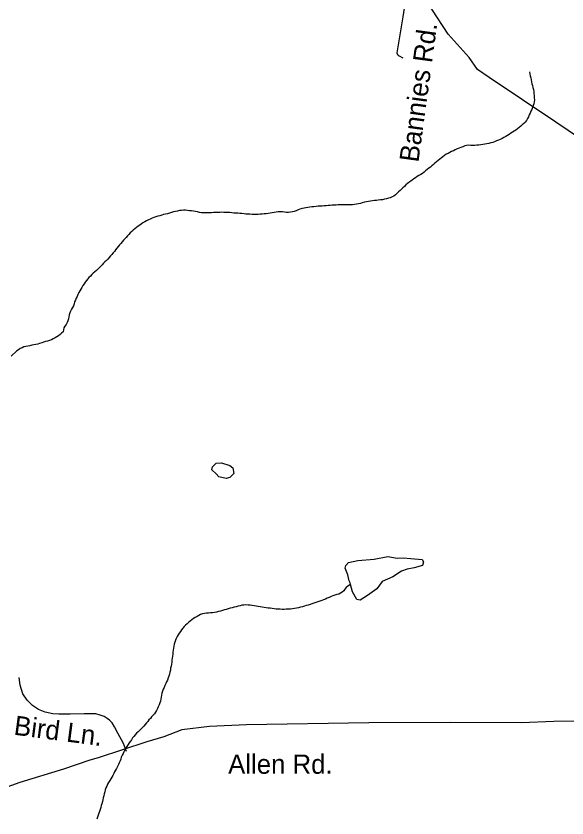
# Model space of a CAD drawing. Extents: x 1950930 to 2061844, y 904556 to 1017002.
# Drawn here: x 1981210 to 1983928, y 931351 to 935305 of the extents above; entities that cross this region are included whole.
import ezdxf

# ---------------------------------------------------------------- set-up
doc = ezdxf.new("R2010")
doc.units = 0
for name, color, linetype in [('Exist Hydrographic Creek Single Shore', 7, 'Continuous'), ('Exist Hydrographic Misc Water Feature', 7, 'Continuous'), ('Exist Road Non-System Type 51', 7, 'Continuous'), ('Exist Road Non-System Type 51 Label', 7, 'Continuous'), ('Exist Road Secondary Type 51 Attributed', 7, 'Continuous'), ('Exist Road Secondary Type 51 Label', 7, 'Continuous')]:
    doc.layers.add(name, color=color, linetype=linetype)

msp = doc.modelspace()

# ---------------------------------------------------------------- linework, layer by layer
at = {"layer": 'Exist Hydrographic Creek Single Shore'}
for points in [[(1983743, 935030.5), (1983745.2, 935020.5), (1983746.9, 935010.4), (1983749.1, 935000.4), (1983751.2, 934990.7), (1983753.4, 934980.7), (1983755.3, 934971.1), (1983757.5, 934961.7), (1983759.8, 934952.1), (1983762.2, 934941.9), (1983764.1, 934932.4), (1983765.3, 934922.5), (1983766.3, 934912.5), (1983766.9, 934901.9), (1983767.6, 934892.1), (1983766.3, 934882.1), (1983764.3, 934872.2), (1983761.8, 934863.3), (1983758.1, 934853.7), (1983754.4, 934843.7), (1983750.3, 934835), (1983746.6, 934825.8), (1983742.3, 934817.2), (1983737.6, 934807.3), (1983732.9, 934799.1), (1983727.6, 934790.2), (1983721.6, 934782.2), (1983715.3, 934774.6), (1983707.7, 934767.7), (1983700.3, 934761.1), (1983692.3, 934754.9), (1983684.3, 934749.3), (1983675.9, 934742.8), (1983667.9, 934738), (1983659.3, 934732.4), (1983650.7, 934726.7), (1983642.7, 934721.5), (1983634.9, 934715.8), (1983625.9, 934710.2), (1983617.1, 934705.5), (1983607.8, 934701.6), (1983599, 934696.9), (1983589.8, 934693), (1983580.8, 934689.1), (1983571.1, 934685.3), (1983561.7, 934681.8), (1983552.3, 934678.9), (1983543, 934676.6), (1983533, 934675.3), (1983522.7, 934672.8), (1983513.1, 934671.4), (1983503.3, 934670), (1983493.2, 934668.7), (1983483.2, 934667.5), (1983473.3, 934666.6), (1983463.5, 934665.9), (1983453.4, 934667.1), (1983442.8, 934667.5), (1983432.9, 934666.6), (1983423.7, 934664.3), (1983414.5, 934660.4), (1983405, 934657.4), (1983395.4, 934653.5), (1983386.8, 934649.6), (1983377.1, 934645.9), (1983367.9, 934640.7), (1983359.1, 934636.8), (1983350.3, 934632.4), (1983341.5, 934627.3), (1983332.6, 934623), (1983324.4, 934617.3), (1983316.4, 934610.8), (1983308.5, 934605.1), (1983300, 934598.7), (1983292.7, 934592.5), (1983284.9, 934586), (1983276.9, 934579.5), (1983269.5, 934573.3), (1983262.1, 934566.7), (1983254.1, 934560.2), (1983246.7, 934554.1), (1983238.9, 934547.5), (1983230.9, 934541.1), (1983223.4, 934535.7), (1983214.9, 934529.3), (1983206.3, 934523.6), (1983197.9, 934518.8), (1983189.7, 934513.2), (1983181.5, 934507.5), (1983173.3, 934501.5), (1983164.7, 934495.9), (1983157.1, 934490.1), (1983148.7, 934483.8), (1983141.1, 934478.4), (1983133.1, 934471.9), (1983126.2, 934465.2), (1983118.6, 934458.2), (1983111.2, 934451.7), (1983104.4, 934444.6), (1983096.6, 934438)], [(1983096.6, 934438), (1983089.3, 934430.6), (1983082.3, 934423.6), (1983074.7, 934417), (1983065.9, 934412.7), (1983056.6, 934408.4), (1983047, 934406.2), (1983037.4, 934404.1), (1983027.1, 934401.9), (1983017.5, 934399.4), (1983007.4, 934398), (1982997.4, 934396.7), (1982987.7, 934395.4), (1982977.9, 934394.9), (1982967.9, 934393.1), (1982958, 934391.8), (1982948.4, 934390.4), (1982938.3, 934389.1), (1982928.5, 934386.5), (1982918.4, 934384.4), (1982909, 934381.3), (1982899.8, 934379.1), (1982889.7, 934377.4), (1982879.7, 934376.1), (1982869.6, 934374.8), (1982859.8, 934374.3), (1982850.2, 934374.5), (1982839.7, 934373.6), (1982830.1, 934373.8), (1982819.8, 934374.3), (1982809.6, 934373.7), (1982799.7, 934373.6), (1982789.9, 934373.1), (1982779.6, 934372.6), (1982769.8, 934371.7), (1982759.9, 934371.2), (1982749.7, 934370.7), (1982739.6, 934369.7), (1982729.6, 934368.4), (1982719.7, 934367.9), (1982709.9, 934367.4), (1982700.1, 934366.9), (1982690, 934365.1), (1982679.8, 934364.7), (1982669.7, 934363.4), (1982659.9, 934362.9), (1982649.8, 934361.1), (1982640.2, 934359.7), (1982630.8, 934358.4), (1982620.9, 934355.4), (1982610.9, 934352), (1982601.8, 934348.9), (1982592.4, 934345.1), (1982582.8, 934341.2), (1982573.5, 934339), (1982563.9, 934337.7), (1982553.7, 934336.8), (1982543.8, 934337), (1982533.8, 934338.2), (1982523.9, 934339.3), (1982513.7, 934339.2), (1982503.8, 934338.7), (1982493.8, 934337.3), (1982483.7, 934336), (1982473.7, 934334.4), (1982464, 934332.9), (1982454.2, 934331.6), (1982444.6, 934330.3), (1982434.1, 934329.4), (1982424.3, 934328), (1982414.4, 934327.5), (1982404.2, 934327.1), (1982394.1, 934326.2), (1982384.9, 934326.4), (1982374.2, 934326.7), (1982364.2, 934327.8), (1982354.5, 934328.1), (1982344.5, 934328.8), (1982334.9, 934329.9), (1982324.4, 934331.1), (1982314.4, 934332.1), (1982304.7, 934332.4), (1982294.7, 934333.1), (1982284.4, 934333.5), (1982274.8, 934334.5), (1982264.9, 934335.6), (1982254.7, 934335.6), (1982244.4, 934335.9), (1982234.4, 934337), (1982224.8, 934337.2), (1982214.9, 934336.3), (1982204.7, 934336.6), (1982194.8, 934336.1), (1982185, 934335.6), (1982174.7, 934334.8), (1982164.5, 934335.1), (1982155, 934334.5), (1982144.8, 934334.1), (1982134.5, 934334), (1982124.9, 934334.2)], [(1982124.9, 934334.2), (1982114.8, 934336.1), (1982105.2, 934338.8), (1982095.8, 934340.6), (1982085.5, 934342.7), (1982075.5, 934344.1), (1982065.4, 934345.2), (1982055.4, 934346.4), (1982045.5, 934347.5), (1982035.7, 934347.8), (1982025.9, 934346.9), (1982016.2, 934345.4), (1982006.2, 934343.3), (1981996.3, 934341.1), (1981986.7, 934339), (1981977.3, 934335.6), (1981967.4, 934333.4), (1981957.6, 934330.4), (1981947.9, 934328.2), (1981938.1, 934326.1), (1981928.9, 934323.4), (1981919, 934320.4), (1981909.2, 934318.3), (1981899.3, 934315.3), (1981890.1, 934311), (1981881.3, 934307.9), (1981872.1, 934304), (1981862.8, 934299.4), (1981853.6, 934295.5), (1981845, 934289.9), (1981836.2, 934285.2), (1981828, 934279.5), (1981820, 934274.3), (1981811.8, 934268.6), (1981803.8, 934262.1), (1981796, 934255.9), (1981788.6, 934249.4), (1981781, 934242), (1981773.6, 934235.8), (1981766.9, 934228.4), (1981759.7, 934221.3), (1981752.9, 934213.8), (1981746.2, 934206.7), (1981739.4, 934199.7), (1981733, 934191.3), (1981726.3, 934184.2), (1981719.9, 934176.2), (1981714, 934169), (1981707.4, 934160.7), (1981701, 934152.7), (1981695.1, 934144.7), (1981689.2, 934137.4), (1981682.8, 934129.5), (1981676.4, 934121.9), (1981669.5, 934114), (1981662.7, 934106.6), (1981655.7, 934099.6), (1981648.6, 934092.9), (1981642, 934085.9), (1981634.8, 934078.8), (1981627.6, 934071.3), (1981620.9, 934064.2), (1981613.7, 934056.8), (1981606.7, 934050.6), (1981598.7, 934044), (1981591.1, 934036.7), (1981583.3, 934030.6), (1981576.6, 934023.1), (1981570, 934016), (1981563.7, 934008.9), (1981557.1, 934000.4), (1981551.2, 933992.5), (1981545.6, 933984.4), (1981539.9, 933976.4), (1981534.5, 933967.3), (1981529.8, 933958.4), (1981524.9, 933949.8), (1981520.2, 933941.6), (1981515.5, 933931.8), (1981511.4, 933922.6), (1981507.5, 933913.9), (1981503, 933904.8), (1981498.9, 933896.1), (1981496.4, 933886.3), (1981493.9, 933876.6), (1981489.4, 933867.5), (1981483.5, 933859.5), (1981478.2, 933850.6), (1981474.9, 933841.3), (1981472.4, 933831.5), (1981470.6, 933822.1), (1981468.3, 933812.3), (1981465.4, 933802.2), (1981461.5, 933793.4), (1981456.6, 933784.4), (1981451.3, 933776.3), (1981446.4, 933767.3), (1981444.3, 933757.5), (1981441.9, 933747.7), (1981434.9, 933741.5)], [(1981434.9, 933741.5), (1981427.5, 933734.9), (1981419.1, 933728.4), (1981411.1, 933723.2), (1981402.5, 933717.6), (1981393.3, 933712.9), (1981384.2, 933707.7), (1981375.4, 933705.1), (1981365.6, 933702.5), (1981355.7, 933699.5), (1981345.9, 933697.4), (1981336.7, 933694.3), (1981326.6, 933690.9), (1981317.2, 933687.9), (1981308, 933685.7), (1981297.7, 933683.5), (1981288.1, 933681.4), (1981278.6, 933678.7), (1981268.4, 933677.5), (1981259, 933675.2), (1981248.9, 933673.2), (1981239.7, 933669.3), (1981230.7, 933665.4), (1981222, 933659.8), (1981213.8, 933654.1), (1981186.6, 933628.3)]]:
    msp.add_lwpolyline(points, dxfattribs=at)
at = {"layer": 'Exist Hydrographic Misc Water Feature'}
for points in [[(1982196.7, 933099.7), (1982224.5, 933102.3), (1982264.7, 933088.5), (1982278.9, 933078.2), (1982285.2, 933050), (1982265.4, 933029.9), (1982247.3, 933024.2), (1982211, 933033.7), (1982196.9, 933048.1), (1982176.8, 933068.2), (1982178.8, 933082.1), (1982196.7, 933099.7)], [(1982860.6, 932502.7), (1982859, 932510.6), (1982853, 932520.9), (1982846.5, 932550.3), (1982834.6, 932582.6), (1982836.4, 932596.6), (1982850.2, 932610.3), (1982896.1, 932620.8), (1982976.3, 932627.2), (1983043.7, 932640), (1983090.1, 932632.6), (1983120.2, 932634.1), (1983158.4, 932631.2), (1983213.7, 932624.8), (1983219.9, 932613.3), (1983216, 932595.2), (1983173.9, 932584.6), (1983140.3, 932578.7), (1983112.2, 932568.8), (1983068.7, 932540.1), (1983017.1, 932517.5), (1982989.2, 932481.1), (1982943.3, 932447.6), (1982907.6, 932424.5), (1982891.8, 932429), (1982869.6, 932466.5), (1982860.6, 932502.7)], [(1982860.6, 932502.7), (1982846.5, 932493.9), (1982839.1, 932487.4), (1982832.9, 932479.4), (1982827, 932471.3), (1982819.8, 932464.3), (1982811.4, 932459.1), (1982802.2, 932455.2), (1982792.7, 932452.2), (1982782.9, 932449.2), (1982773.5, 932446.2), (1982764, 932442.4), (1982755.2, 932438.4), (1982745.6, 932434.2), (1982736.4, 932430.3), (1982726.9, 932427.3), (1982717.9, 932423.4), (1982708.5, 932420.3), (1982698.8, 932416.5), (1982689.4, 932413.4), (1982680, 932410.5), (1982670.1, 932407.5), (1982660.7, 932404.1), (1982651.3, 932401), (1982641.8, 932398), (1982632.4, 932395), (1982622.8, 932392.8), (1982612.9, 932390.3), (1982603.3, 932388), (1982593, 932386), (1982583.6, 932384.5), (1982573.3, 932382.8), (1982563.9, 932381.5), (1982553.7, 932380.9), (1982543.4, 932380.5), (1982533.4, 932379.6), (1982523.7, 932379.8), (1982513.5, 932380.2), (1982503.4, 932381.3), (1982493.8, 932381.2), (1982483.7, 932382.3), (1982473.9, 932384.2), (1982463.8, 932385.4), (1982454.2, 932386.4), (1982443.7, 932387.9), (1982434.3, 932388.9), (1982423.9, 932391), (1982414.4, 932392), (1982404.4, 932394), (1982394.5, 932395.8), (1982384.5, 932396.9), (1982374.6, 932398.5), (1982364.6, 932399.6), (1982355, 932400.6), (1982344.5, 932401.9), (1982334.2, 932400.9), (1982324.6, 932399.6), (1982315.4, 932397.4), (1982305.3, 932396), (1982295.9, 932392.9), (1982286.3, 932390.4), (1982276.4, 932387.4), (1982267, 932385.2), (1982257.1, 932382.3), (1982247.3, 932379.3), (1982238.1, 932377.1), (1982228.6, 932373.6), (1982218.8, 932370.6), (1982209, 932368.4), (1982199.3, 932366.3), (1982189.5, 932363.7), (1982179.4, 932362.4), (1982169.2, 932361.9), (1982159.3, 932361), (1982149.1, 932360.5), (1982139.4, 932359.1), (1982129.4, 932357.1), (1982120.4, 932354), (1982111.4, 932349.2), (1982103.2, 932345.2), (1982094.5, 932339.6), (1982085.5, 932334.1), (1982077.7, 932327.5), (1982069.7, 932321.1), (1982061.5, 932315), (1982054.1, 932308.4), (1982046.6, 932301.8), (1982039.6, 932294.8), (1982032.8, 932287.8), (1982026.7, 932279.2), (1982021.1, 932271.2), (1982015.4, 932262.3), (1982010.3, 932254.2), (1982005.3, 932245.6), (1982000.8, 932236.6), (1981996.7, 932227.5), (1981993.5, 932217.8), (1981991, 932208), (1981988.9, 932198.1), (1981987.3, 932188.3)], [(1981987.3, 932188.3), (1981985.7, 932178.4), (1981984.4, 932168.8), (1981982.8, 932158.9), (1981981.6, 932148.9), (1981980.3, 932138.6), (1981979.1, 932128.6), (1981977.9, 932118.7), (1981976.2, 932108.8), (1981974.6, 932099.3), (1981972.9, 932089.4), (1981971.3, 932079.5), (1981968.8, 932069.8), (1981966.8, 932059.9), (1981963.9, 932050.2), (1981960.6, 932041.4), (1981957, 932031.3), (1981952.9, 932022.6), (1981948.3, 932013.6), (1981944.4, 932004.5), (1981940.1, 931994.9), (1981936.7, 931985.8), (1981932.6, 931977), (1981930.1, 931967.3), (1981928, 931957.4), (1981926.4, 931947.6), (1981924.8, 931937.6), (1981922.3, 931927.9), (1981919.4, 931918.1), (1981915.7, 931908.6), (1981912, 931899.4), (1981907.9, 931890.3), (1981903.4, 931881.6), (1981898.1, 931872.7), (1981892.4, 931865.4), (1981885.4, 931857.1), (1981879, 931850.1), (1981872.7, 931842.1), (1981865.9, 931834.6), (1981860, 931826.6), (1981853.2, 931819.5), (1981846.8, 931811.5), (1981840.1, 931804), (1981833.3, 931797), (1981826.1, 931789.5), (1981819.2, 931783.2), (1981812, 931775.8), (1981804.8, 931768.8), (1981797.6, 931761.4), (1981791.7, 931753.4), (1981785.3, 931746.2), (1981779.6, 931737.3), (1981774, 931729.2), (1981768.3, 931721.2), (1981762.8, 931713.1), (1981757.4, 931704.2), (1981752.3, 931696), (1981747.4, 931687.1), (1981742.5, 931678), (1981737.8, 931669.4), (1981733.7, 931660.3), (1981729.1, 931651.3), (1981726.3, 931641.5), (1981723.4, 931632.6), (1981719.3, 931622.7), (1981714.8, 931614.1), (1981709.9, 931605), (1981705.6, 931596), (1981701, 931587.7), (1981696.3, 931579.1), (1981691.8, 931570.1), (1981686.9, 931561), (1981682, 931552), (1981677.3, 931543.5), (1981672.3, 931535.3), (1981666.6, 931526.4), (1981662.1, 931517.4), (1981657.8, 931508.2), (1981653.7, 931499.5), (1981650.4, 931489.5), (1981647.5, 931480.6), (1981645.1, 931470.8), (1981642.6, 931461.1), (1981640.1, 931451.2), (1981638.1, 931441.5), (1981636, 931431.7), (1981633.6, 931421.8), (1981630.7, 931412.2), (1981627.8, 931403.3), (1981624.6, 931393.6), (1981621.3, 931383.6), (1981618, 931374.7), (1981615.1, 931365), (1981611.9, 931355), (1981609, 931346)]]:
    msp.add_lwpolyline(points, dxfattribs=at)
at = {"layer": 'Exist Road Non-System Type 51'}
for points in [[(1983171.1, 935488.1), (1983160.2, 935473.2), (1983153, 935457.9), (1983144.9, 935440.8), (1983138.6, 935417.3), (1983132.2, 935387.6), (1983118.8, 935300.1), (1983088.5, 935122.8), (1983091.2, 935115.6), (1983094.9, 935111.1), (1983100.2, 935108.3), (1983118.2, 935098.4)], [(1981755.8, 931678.4), (1981739.4, 931718.6), (1981712.8, 931769.2), (1981695.9, 931801.1), (1981684.2, 931819.8), (1981671, 931834), (1981660.4, 931842), (1981645.2, 931851.8), (1981625.8, 931858.9), (1981603.5, 931864.2), (1981582.2, 931864.2), (1981546.6, 931864.2), (1981476.5, 931862.4), (1981420.6, 931863.3), (1981391.2, 931864.2), (1981354, 931873.1), (1981321.1, 931886.4), (1981291.9, 931905.9), (1981264.2, 931932.6), (1981243.9, 931962.8), (1981230.5, 932005.4), (1981225.2, 932043.6)]]:
    msp.add_lwpolyline(points, dxfattribs=at)
at = {"layer": 'Exist Road Secondary Type 51 Attributed'}
for points in [[(1984256.4, 934486.6), (1984248.2, 934528), (1983873.6, 934781.7), (1983543.4, 935001.5), (1983486.2, 935041.9), (1983446.2, 935100.1), (1983342.2, 935214.7), (1983135, 935533.7), (1983056.8, 935618), (1982987.6, 935661.7), (1982924.4, 935685.8), (1982834.7, 935700.8), (1982640.9, 935757.4), (1982485.9, 935796.5), (1982365.5, 935838.6), (1982261.7, 935882.3), (1982050.4, 935994.7), (1981907.5, 936069.7), (1981832.3, 936125.4), (1981790.1, 936170.6), (1981740.5, 936232.3), (1981683.3, 936320.4), (1981619.4, 936433.3)], [(1984215.7, 931830.7), (1983863.5, 931826.1), (1983703.3, 931820.8), (1983354.1, 931822.3), (1982951, 931820), (1982347.5, 931810.1), (1982165.3, 931802.5), (1982028.7, 931785.8), (1981939.1, 931750.9), (1981855.6, 931726.6), (1981615.7, 931647.5), (1981574.7, 931636.9), (1981444.2, 931591.3), (1981228.6, 931526), (1981081.3, 931474.3)]]:
    msp.add_lwpolyline(points, dxfattribs=at)

# ---------------------------------------------------------------- texts
at = {"layer": 'Exist Road Non-System Type 51 Label'}
for s, rotation, p in [('Bannies Rd.', 82.2381, (1983194.9, 934580.5)), ('Yellow Bird Ln.', 352.5576, (1980789.9, 931815.3))]:
    msp.add_text(s, height=95, rotation=rotation, dxfattribs=at).set_placement(p)
at = {"layer": 'Exist Road Secondary Type 51 Label'}
msp.add_text('Allen Rd.', height=95, dxfattribs=at).set_placement((1982256.5, 931569.1))

doc.saveas('drawing.dxf')
